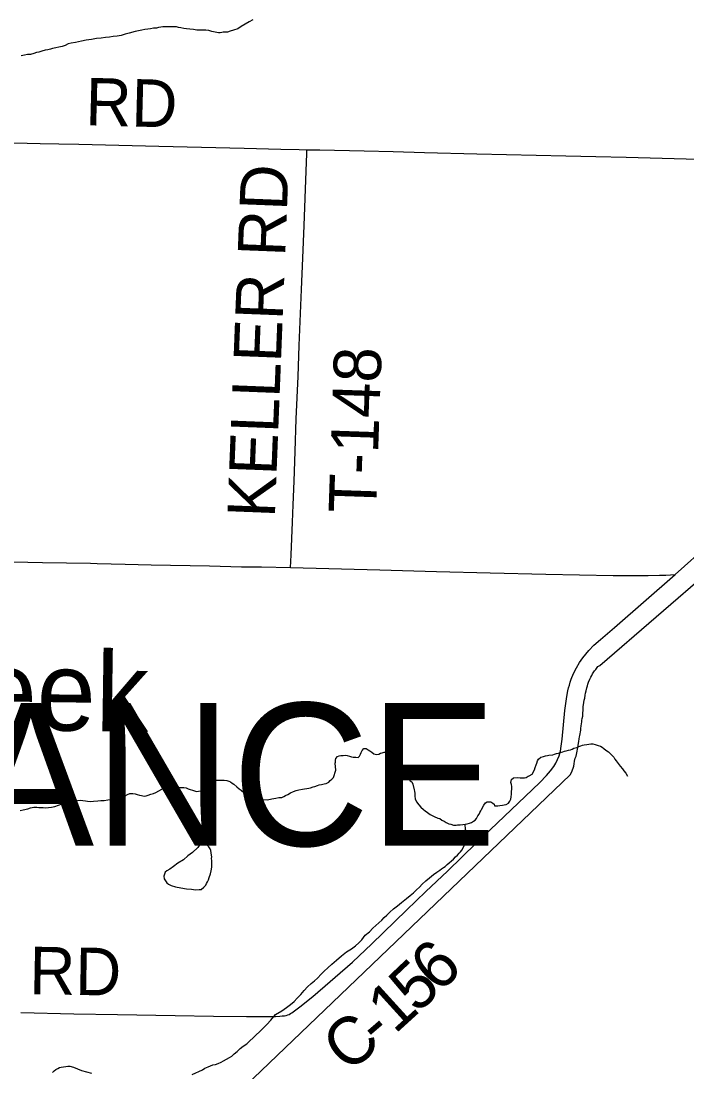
# Model space of a CAD drawing. Extents: x -483 to 680, y 0 to 440.
# Drawn here: x 160.7 to 200.5, y 248.8 to 311.6 of the extents above; entities that cross this region are included whole.
import ezdxf

# ---------------------------------------------------------------- set-up
doc = ezdxf.new("R2010")
doc.units = 0
for name, color, linetype in [('GM_X_County_Road', 7, 'Continuous'), ('GM_X_County_Road_Text', 7, 'Continuous'), ('GM_X_Minor_Lake', 7, 'Continuous'), ('GM_X_Minor_River', 7, 'Continuous'), ('GM_X_Minor_River_Text', 7, 'Continuous'), ('GM_X_Township_Road', 7, 'Continuous'), ('GM_X_Township_Road_Text', 7, 'Continuous'), ('GM_X_Township_Text', 7, 'Continuous')]:
    doc.layers.add(name, color=color, linetype=linetype)

msp = doc.modelspace()

# ---------------------------------------------------------------- linework, layer by layer
at = {"layer": 'GM_X_County_Road'}
for points in [[(199.794, 278.543), (201.845, 280.377), (203.117, 281.425), (204.923, 282.948), (206.976, 284.71), (209.908, 287.214), (211.937, 288.957), (214.16, 290.855), (216.4, 292.781), (217.497, 293.705), (218.002, 294.15), (218.689, 294.733), (218.846, 294.87)], [(159.327, 279.332), (161.968, 279.265), (164.828, 279.222), (165.231, 279.213), (166.909, 279.174), (168.463, 279.126), (171.944, 279.073), (173.87, 279.019), (175.052, 279), (176.798, 278.974)], [(176.798, 278.974), (182.136, 278.828), (185.523, 278.739), (188.723, 278.655), (192.049, 278.57), (196.081, 278.501), (197.534, 278.49), (198.178, 278.494), (198.854, 278.503), (199.221, 278.516), (199.51, 278.528), (199.794, 278.543)], [(176.864, 252.341), (177.346, 252.711), (178.13, 253.323), (180.495, 255.381), (181.645, 256.471), (183.729, 258.474), (184.89, 259.597), (186.169, 260.824), (187.912, 262.508), (190.813, 265.275), (191.687, 266.115), (192.102, 266.531), (192.341, 266.812), (192.527, 267.069), (192.648, 267.267), (192.759, 267.486), (192.846, 267.715), (192.927, 267.989), (192.978, 268.295), (193.024, 268.712), (193.193, 270.414), (193.299, 271.12), (193.336, 271.378), (193.376, 271.589), (193.418, 271.774), (193.461, 271.929), (193.513, 272.114), (193.577, 272.286), (193.712, 272.626), (193.881, 272.963), (194.071, 273.287), (194.264, 273.573), (194.436, 273.797), (194.621, 274.01), (194.932, 274.32), (195.326, 274.674), (196.162, 275.373), (199.794, 278.543)]]:
    msp.add_lwpolyline(points, dxfattribs=at)
at = {"layer": 'GM_X_Minor_Lake'}
for points in [[(171.48, 262.644), (171.459, 262.569), (171.258, 262.233), (170.925, 261.94), (170.652, 261.74), (170.396, 261.482), (170.047, 261.284), (169.793, 261.102), (169.579, 260.938), (169.404, 260.83), (169.306, 260.757), (169.222, 260.512), (169.236, 260.36), (169.4, 260.107), (169.492, 260.028), (169.662, 259.965), (169.907, 259.881), (170.228, 259.813), (170.569, 259.764), (170.873, 259.735), (171.12, 259.708)], [(171.48, 262.644), (171.459, 262.569), (171.258, 262.233), (170.925, 261.94), (170.652, 261.74), (170.396, 261.482), (170.047, 261.284), (169.793, 261.102), (169.579, 260.938), (169.404, 260.83), (169.306, 260.757), (169.222, 260.512), (169.236, 260.36), (169.4, 260.107), (169.492, 260.028), (169.662, 259.965), (169.907, 259.881), (170.228, 259.813), (170.569, 259.764), (170.873, 259.735), (171.12, 259.708), (171.33, 259.72), (171.444, 259.716), (171.601, 259.863), (171.719, 259.973), (171.76, 260.067), (171.82, 260.179), (171.881, 260.291), (171.924, 260.442), (172.007, 260.648), (172.051, 260.837), (172.077, 261.046), (172.084, 261.274), (172.089, 261.445), (172.075, 261.578), (172.078, 261.673), (172.062, 261.769), (172.047, 261.903), (172.033, 262.055), (171.979, 262.152), (171.906, 262.269), (171.48, 262.644)], [(171.12, 259.708), (171.33, 259.72), (171.444, 259.716), (171.601, 259.863), (171.719, 259.973), (171.76, 260.067), (171.82, 260.179), (171.881, 260.291), (171.924, 260.442), (172.007, 260.648), (172.051, 260.837), (172.077, 261.046), (172.084, 261.274), (172.089, 261.445), (172.075, 261.578), (172.078, 261.673), (172.062, 261.769), (172.047, 261.903), (172.033, 262.055), (171.979, 262.152), (171.906, 262.269), (171.48, 262.644)]]:
    msp.add_lwpolyline(points, dxfattribs=at)
at = {"layer": 'GM_X_Minor_River'}
for points in [[(195.284, 273.119), (289.59, 354.596)], [(174.54, 311.723), (174.309, 311.596), (174.077, 311.45), (173.846, 311.323), (173.634, 311.176), (173.385, 311.106), (173.174, 311.036), (173.021, 310.983), (172.869, 310.968), (172.774, 310.97), (172.678, 310.954), (172.583, 310.937), (172.488, 310.939), (172.28, 310.983), (172.091, 311.025), (171.903, 311.068), (171.732, 311.092), (171.58, 311.095), (171.429, 311.099), (171.182, 311.106), (170.992, 311.129), (170.765, 311.154), (170.576, 311.178), (170.405, 311.201), (170.236, 311.244), (170.084, 311.266), (169.971, 311.288), (169.838, 311.292), (169.648, 311.296), (169.477, 311.301), (169.325, 311.305), (169.154, 311.29), (169.04, 311.274), (168.906, 311.258), (168.773, 311.224), (168.601, 311.209), (168.429, 311.176), (168.258, 311.161), (168.086, 311.127), (167.896, 311.094), (167.705, 311.061), (167.495, 311.009), (167.151, 310.923), (166.902, 310.853), (166.672, 310.783), (166.424, 310.733), (166.196, 310.72), (165.967, 310.687), (165.739, 310.655), (165.472, 310.624), (165.186, 310.593), (164.9, 310.544), (164.576, 310.495), (164.29, 310.445), (163.927, 310.36), (163.679, 310.328), (163.488, 310.276), (163.315, 310.185), (163.142, 310.114), (162.569, 309.995), (162.435, 309.961), (162.283, 309.927), (162.13, 309.892), (161.92, 309.841), (161.747, 309.788), (161.595, 309.754), (161.441, 309.701), (161.25, 309.649), (161.06, 309.635), (160.888, 309.601), (160.678, 309.569)], [(193.508, 266.565), (193.605, 266.762), (193.646, 266.875), (193.686, 266.969), (193.728, 267.101), (193.75, 267.233), (193.773, 267.385), (193.815, 267.573), (193.875, 267.686), (193.899, 267.894), (193.921, 267.989), (193.943, 268.102), (193.964, 268.196), (193.986, 268.329), (194.009, 268.461), (194.03, 268.574), (194.053, 268.726), (194.075, 268.839), (194.077, 268.934), (194.099, 269.028), (194.121, 269.142), (194.142, 269.236), (194.145, 269.369), (194.167, 269.483), (194.19, 269.634), (194.211, 269.728), (194.214, 269.823), (194.235, 269.937), (194.258, 270.088), (194.261, 270.202), (194.263, 270.297), (194.285, 270.41), (194.288, 270.543), (194.291, 270.657), (194.313, 270.751), (194.335, 270.903), (194.339, 271.035), (194.38, 271.167), (194.403, 271.338), (194.425, 271.451), (194.467, 271.602), (194.509, 271.772), (194.551, 271.904), (194.572, 271.998), (194.613, 272.111), (194.693, 272.299), (194.753, 272.411), (194.812, 272.505), (194.853, 272.618), (194.971, 272.786), (195.05, 272.879), (195.168, 273.047), (195.284, 273.119)], [(191.229, 266.612), (191.386, 266.875), (191.408, 267.008), (191.469, 267.177), (191.51, 267.271), (191.551, 267.403), (191.611, 267.515), (191.747, 267.626), (191.919, 267.678), (192.034, 267.713), (192.148, 267.73), (192.243, 267.746), (192.472, 267.778), (192.568, 267.814), (192.683, 267.849), (192.816, 267.865), (192.912, 267.9), (193.065, 267.953), (193.18, 267.988), (193.276, 268.005), (193.409, 268.039), (193.524, 268.075), (193.62, 268.11), (193.735, 268.164), (193.908, 268.217), (194.023, 268.271), (194.138, 268.306), (194.252, 268.341), (194.348, 268.358), (194.501, 268.392), (194.615, 268.408), (194.748, 268.423), (194.862, 268.42), (195.013, 268.379), (195.183, 268.336), (195.315, 268.295), (195.427, 268.235), (195.52, 268.157), (195.65, 268.04), (195.8, 267.941), (195.892, 267.844), (196.004, 267.746), (196.115, 267.629), (196.188, 267.513), (196.262, 267.416), (196.5, 267.088), (196.629, 266.932), (196.721, 266.816), (196.832, 266.68), (196.939, 266.5)], [(179.504, 266.847), (179.468, 267.272), (179.47, 267.329), (179.473, 267.443), (179.494, 267.557), (179.592, 267.668), (179.707, 267.703), (179.802, 267.72), (179.936, 267.735), (180.069, 267.751), (180.183, 267.729), (180.314, 267.688), (180.446, 267.646), (180.541, 267.625), (180.693, 267.621), (180.826, 267.618), (180.922, 267.691), (180.982, 267.804), (181.023, 267.917), (181.083, 268.029), (181.18, 268.14), (181.314, 268.156), (181.426, 268.077), (181.538, 267.999), (181.65, 267.92), (181.78, 267.821), (181.932, 267.799), (182.065, 267.814), (182.161, 267.869), (182.276, 267.885), (182.39, 267.92), (182.505, 267.936), (182.62, 267.971), (182.715, 267.969), (182.845, 267.889), (182.881, 267.775), (182.878, 267.661), (182.837, 267.567), (182.794, 267.359), (182.773, 267.265), (182.789, 267.131), (182.881, 267.034), (182.994, 266.993), (183.125, 266.933), (183.219, 266.873), (183.332, 266.833), (183.634, 266.777)], [(74.642, 128.314), (75.587, 153.634), (193.508, 266.565)], [(172.624, 266.259), (172.814, 266.253), (172.985, 266.228), (173.098, 266.205), (173.211, 266.163), (173.304, 266.084), (173.397, 266.024), (173.583, 265.866), (173.73, 265.728), (173.842, 265.648), (174.009, 265.509), (174.102, 265.43), (174.213, 265.35), (174.401, 265.268), (174.609, 265.204), (174.816, 265.14), (175.005, 265.096), (175.424, 265.082), (175.673, 265.131), (175.903, 265.18), (176.094, 265.212), (176.266, 265.225), (176.382, 265.278), (176.498, 265.332), (176.634, 265.403), (176.789, 265.493), (176.963, 265.583), (177.136, 265.634), (177.29, 265.686), (177.501, 265.717), (177.634, 265.732), (177.769, 265.765), (177.883, 265.781), (177.979, 265.796), (178.152, 265.848), (178.249, 265.883), (178.402, 265.935), (178.499, 265.969), (178.652, 266.002), (178.806, 266.035), (178.92, 266.051), (179.076, 266.141), (179.155, 266.233), (179.252, 266.306), (179.351, 266.417), (179.504, 266.847)], [(183.634, 266.777), (183.953, 266.208), (184.046, 266.147), (184.099, 266.013), (184.183, 265.686), (184.199, 265.591), (184.214, 265.457), (184.228, 265.304), (184.242, 265.133), (184.313, 264.959), (184.459, 264.783), (184.588, 264.646), (184.736, 264.508), (184.848, 264.428), (184.978, 264.328), (185.146, 264.209), (185.37, 264.087), (185.595, 263.985), (185.709, 263.962), (185.839, 263.862), (185.97, 263.801), (186.101, 263.721), (186.251, 263.64), (186.383, 263.616), (186.534, 263.573), (186.687, 263.568), (186.782, 263.584), (186.934, 263.579), (187.088, 263.612), (187.222, 263.626), (187.355, 263.641), (187.49, 263.675), (187.606, 263.728), (187.722, 263.8), (187.839, 263.872), (187.918, 263.965), (187.98, 264.115), (188.06, 264.227), (188.101, 264.32), (188.161, 264.413), (188.202, 264.507), (188.343, 264.769), (188.443, 264.899), (188.54, 264.953), (188.655, 264.968), (188.769, 264.964), (188.88, 264.884), (188.974, 264.824), (188.99, 264.728), (189.18, 264.722), (189.295, 264.737), (189.467, 264.77), (189.563, 264.786), (189.677, 264.801), (189.813, 264.872), (189.912, 265.002), (189.954, 265.115), (189.978, 265.267), (190.002, 265.418), (190.007, 265.57), (190.012, 265.722), (190.016, 265.874), (190.001, 265.989), (189.967, 266.123), (189.992, 266.293), (190.129, 266.403), (190.338, 266.415), (190.528, 266.39), (190.642, 266.386), (190.776, 266.401), (190.872, 266.416), (191.007, 266.488), (191.065, 266.505), (191.229, 266.612)], [(160.627, 264.45), (160.799, 264.482), (161.087, 264.549), (161.241, 264.601), (161.451, 264.632), (161.623, 264.645), (161.736, 264.622), (161.851, 264.618), (162.003, 264.613), (162.155, 264.608), (162.327, 264.622), (162.499, 264.635), (162.71, 264.685), (162.921, 264.754), (163.134, 264.842), (163.402, 264.89), (163.574, 264.923), (163.709, 264.956), (163.863, 265.008), (164.054, 265.04), (164.226, 265.053), (164.378, 265.048), (164.53, 265.024), (164.662, 265.001), (164.833, 264.976), (165.004, 264.99), (165.272, 265.019), (165.444, 265.032), (165.654, 265.044), (165.864, 265.075), (166.075, 265.106), (166.246, 265.12), (166.4, 265.153), (166.572, 265.185), (166.745, 265.236), (166.901, 265.326), (167.036, 265.398), (167.19, 265.45), (167.362, 265.463), (167.494, 265.44), (167.626, 265.397), (167.758, 265.355), (167.872, 265.332), (167.966, 265.31), (168.061, 265.307), (168.157, 265.322), (168.273, 265.357), (168.445, 265.408), (168.599, 265.46), (168.734, 265.513), (169.103, 265.71), (169.218, 265.763), (169.315, 265.798), (169.469, 265.85), (169.565, 265.866), (169.678, 265.843), (169.944, 265.834), (170.192, 265.826), (170.42, 265.818), (170.553, 265.795), (170.665, 265.734), (170.797, 265.692), (170.929, 265.649), (171.042, 265.608), (171.174, 265.584), (171.289, 265.599), (171.423, 265.614), (171.577, 265.666), (171.673, 265.701), (171.79, 265.773), (171.948, 265.958), (172.067, 266.106), (172.146, 266.199), (172.357, 266.249), (172.624, 266.259)], [(173.278, 249.763), (173.415, 249.892), (173.61, 250.037), (173.787, 250.203), (173.963, 250.349), (174.177, 250.494), (174.354, 250.66), (174.55, 250.843), (174.746, 251.027), (174.943, 251.211), (175.159, 251.432), (175.376, 251.653), (175.613, 251.911), (175.89, 252.245), (176.277, 252.46), (176.55, 252.66), (176.785, 252.843), (177, 253.026), (177.197, 253.229), (177.414, 253.45), (177.611, 253.672), (177.809, 253.893), (178.024, 254.095), (178.22, 254.26), (178.397, 254.426), (178.632, 254.646), (178.81, 254.83), (179.026, 255.033), (179.261, 255.253), (179.535, 255.491), (179.848, 255.747), (180.141, 255.985), (180.433, 256.165), (180.667, 256.348), (180.882, 256.531), (181.06, 256.715), (181.259, 256.994), (181.513, 257.195), (181.71, 257.398), (182.259, 257.893), (182.397, 258.041), (182.554, 258.188), (182.731, 258.372), (182.947, 258.555), (183.181, 258.738), (183.416, 258.939), (183.728, 259.176), (183.943, 259.359), (184.139, 259.524), (184.316, 259.69), (184.492, 259.855), (184.67, 260.039), (184.886, 260.241), (185.101, 260.424), (185.335, 260.607), (185.53, 260.753), (185.725, 260.879), (185.822, 260.952), (185.939, 261.025), (186.036, 261.097), (186.154, 261.208), (186.272, 261.318), (186.409, 261.428), (186.527, 261.538), (186.645, 261.667), (186.782, 261.777), (186.88, 261.888), (186.96, 261.98), (187.039, 262.073), (187.119, 262.203), (187.201, 262.391), (187.223, 262.485), (187.246, 262.598), (187.269, 262.731), (187.273, 262.864), (187.298, 263.034), (187.283, 263.168), (187.249, 263.302), (187.222, 263.626)], [(170.92, 248.662), (171.537, 248.927), (171.674, 249.036), (171.867, 249.106), (172.002, 249.177), (172.156, 249.229), (172.31, 249.262), (172.464, 249.314), (172.637, 249.385), (172.793, 249.475), (172.967, 249.583), (173.142, 249.672), (173.278, 249.763)], [(162.564, 248.786), (162.662, 248.878), (162.76, 248.951), (162.876, 249.023), (162.973, 249.077), (163.088, 249.092), (163.222, 249.107), (163.356, 249.14), (163.471, 249.156), (163.604, 249.151), (163.811, 249.087), (164.056, 249.003), (164.3, 248.9), (164.602, 248.814), (164.885, 248.728)]]:
    msp.add_lwpolyline(points, dxfattribs=at)
at = {"layer": 'GM_X_Township_Road'}
for points in [[(127.32, 305.184), (127.777, 305.171), (128.895, 305.14), (131.66, 305.068), (134.643, 304.982), (135.793, 304.966), (137.812, 304.921), (140.08, 304.871), (141.354, 304.826), (142.224, 304.815), (143.374, 304.791), (146.233, 304.728), (153.068, 304.547), (157.884, 304.428), (161.83, 304.33), (162.949, 304.309), (164.129, 304.277), (168.914, 304.153), (174.01, 304.032), (176.216, 303.98), (177.302, 303.96), (177.765, 303.951)], [(176.798, 278.974), (176.814, 279.324), (176.833, 279.731), (176.905, 281.687), (176.947, 282.711), (177.007, 284.139), (177.077, 285.909), (177.138, 287.865), (177.241, 290.38), (177.315, 292.242), (177.448, 295.595), (177.531, 297.458), (177.607, 299.414), (177.725, 302.674), (177.758, 303.73), (177.765, 303.951)], [(177.765, 303.951), (177.987, 303.95), (178.546, 303.947), (181.187, 303.882), (182.927, 303.836), (184.791, 303.785), (187.929, 303.709), (193.243, 303.587), (195.045, 303.547), (196.847, 303.501), (204.024, 303.301), (208.498, 303.193), (210.455, 303.142), (212.195, 303.105), (216.607, 303.002), (220.243, 302.924), (221.797, 302.889), (223.568, 302.854), (228.062, 302.769)], [(160.665, 252.367), (163.834, 252.289), (166.444, 252.241), (169.893, 252.191), (172.192, 252.15), (174.15, 252.128), (175.362, 252.13), (175.891, 252.134), (176.146, 252.143), (176.3, 252.155), (176.424, 252.168), (176.531, 252.188), (176.621, 252.217), (176.711, 252.25), (176.794, 252.299), (176.864, 252.341)]]:
    msp.add_lwpolyline(points, dxfattribs=at)

# ---------------------------------------------------------------- texts
at = {"layer": 'GM_X_County_Road_Text'}
for s, rotation, p in [('6', 43.80519, (185.649, 253.467)), ('5', 43.48367, (184.366, 252.25)), ('1', 42.25456, (183.022, 251.028)), ('C', 39.34007, (180.214, 248.685)), ('-', 40.7334, (182.077, 250.212))]:
    msp.add_text(s, height=2.841, rotation=rotation, dxfattribs=at).set_placement(p)
at = {"layer": 'GM_X_Minor_River_Text'}
msp.add_text('Creek', height=4.7372, rotation=359.17665, dxfattribs=at).set_placement((151.386, 269.388))
at = {"layer": 'GM_X_Township_Road_Text'}
for s, rotation, p in [('RD', 358.50887, (164.507, 305.413)), ('KELLER RD', 87.73901, (175.85, 281.914)), ('T-148', 88.03529, (181.902, 282.187)), ('RD', 359.01279, (161.159, 253.462))]:
    msp.add_text(s, height=2.8409, rotation=rotation, dxfattribs=at).set_placement(p)
at = {"layer": 'GM_X_Township_Text'}
msp.add_text('DEFIANCE', height=8.5227, rotation=0.00001, dxfattribs=at).set_placement((131.49, 262.337))

doc.saveas('drawing.dxf')
